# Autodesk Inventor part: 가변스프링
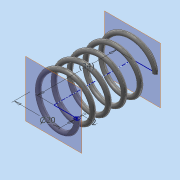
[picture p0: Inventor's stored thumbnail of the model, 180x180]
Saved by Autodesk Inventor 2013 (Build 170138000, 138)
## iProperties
Created: 2019-05
Part Number: 가변스프링
Material: 스테인리스강
Document SubType Name: Modeling
Designer: dgall
Density: 8.08 g/cm^3
Mass: 7.87511 g
Surface Area: 19.7325 cm^2
Volume: 0.974642 cm^3
Author: dgall
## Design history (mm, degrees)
sketch "스케치1"
  geometry: L1 (10, 0)-(0, 0); L2 (0, 0)-(0, 34); L3 (0, 34)-(10, 34); C1 r 1 at (10, 0)
  constraints: 6 end point, 2 parallel, 1 centre point, 1 coincident, 1 horizontal, 1 perpendicular
  dimensions: "d0" = 34 distance of L1.end L2.end (derived); "d1" = 20 diameter of L1.start L2; "d2" = 2 diameter of C1
feature "코일1" sketch "스케치1" pitch "d3" = 10; turns "d5" = 5; dims "d4" = 34 (= d0), "d6" = 0, angle "d7" = 90 deg, angle "d8" = 90 deg, "d9" = 0, "d10" = 0
node "작업 평면2"
  node "작업 평면1"
feature "분할1"
feature "분할2"
node "솔리드1"
other parameters: "d11" = 0
